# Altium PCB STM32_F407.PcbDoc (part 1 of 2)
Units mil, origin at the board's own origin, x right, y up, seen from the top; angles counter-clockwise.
Board outline 2935.42 x 3745.42 mil, 2 copper layers (TopLayer, BottomLayer); 75 components, 133 nets, 531 pads, 175 vias.
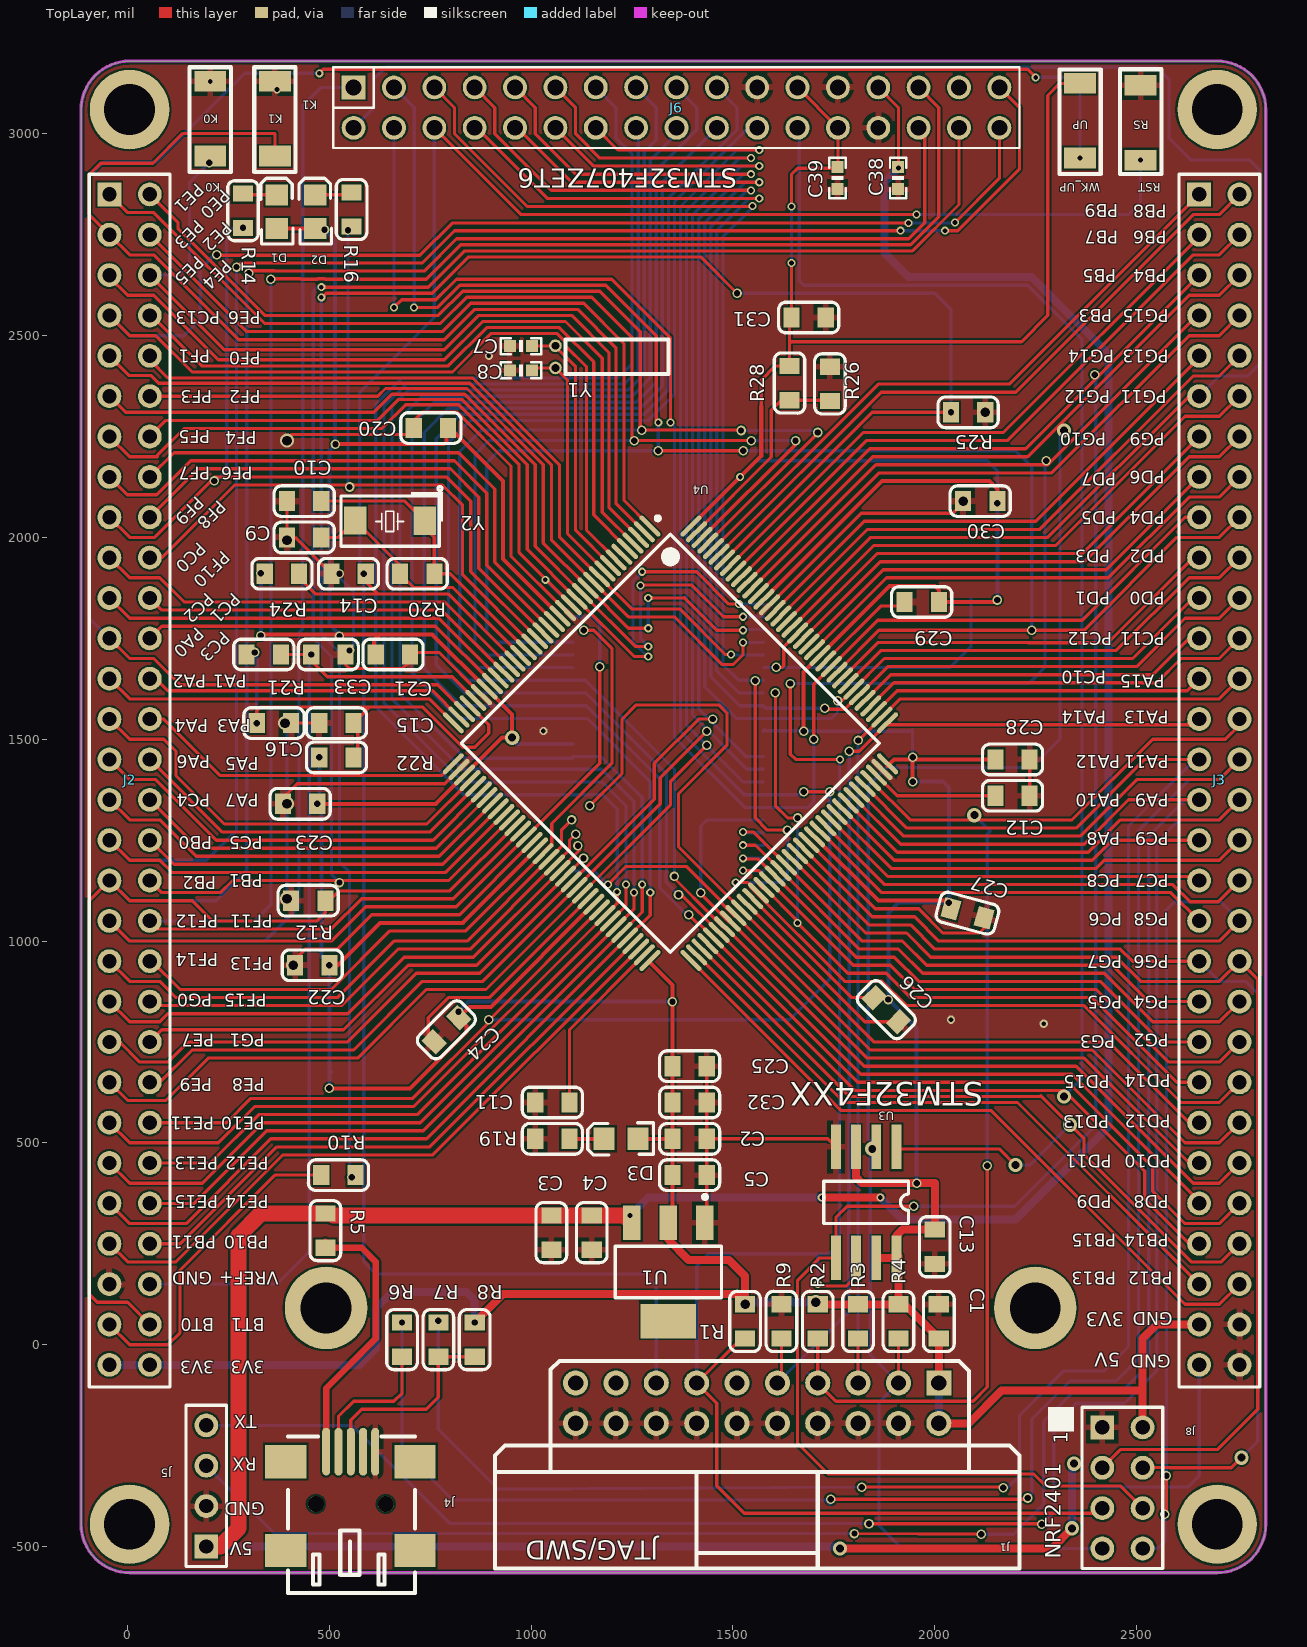
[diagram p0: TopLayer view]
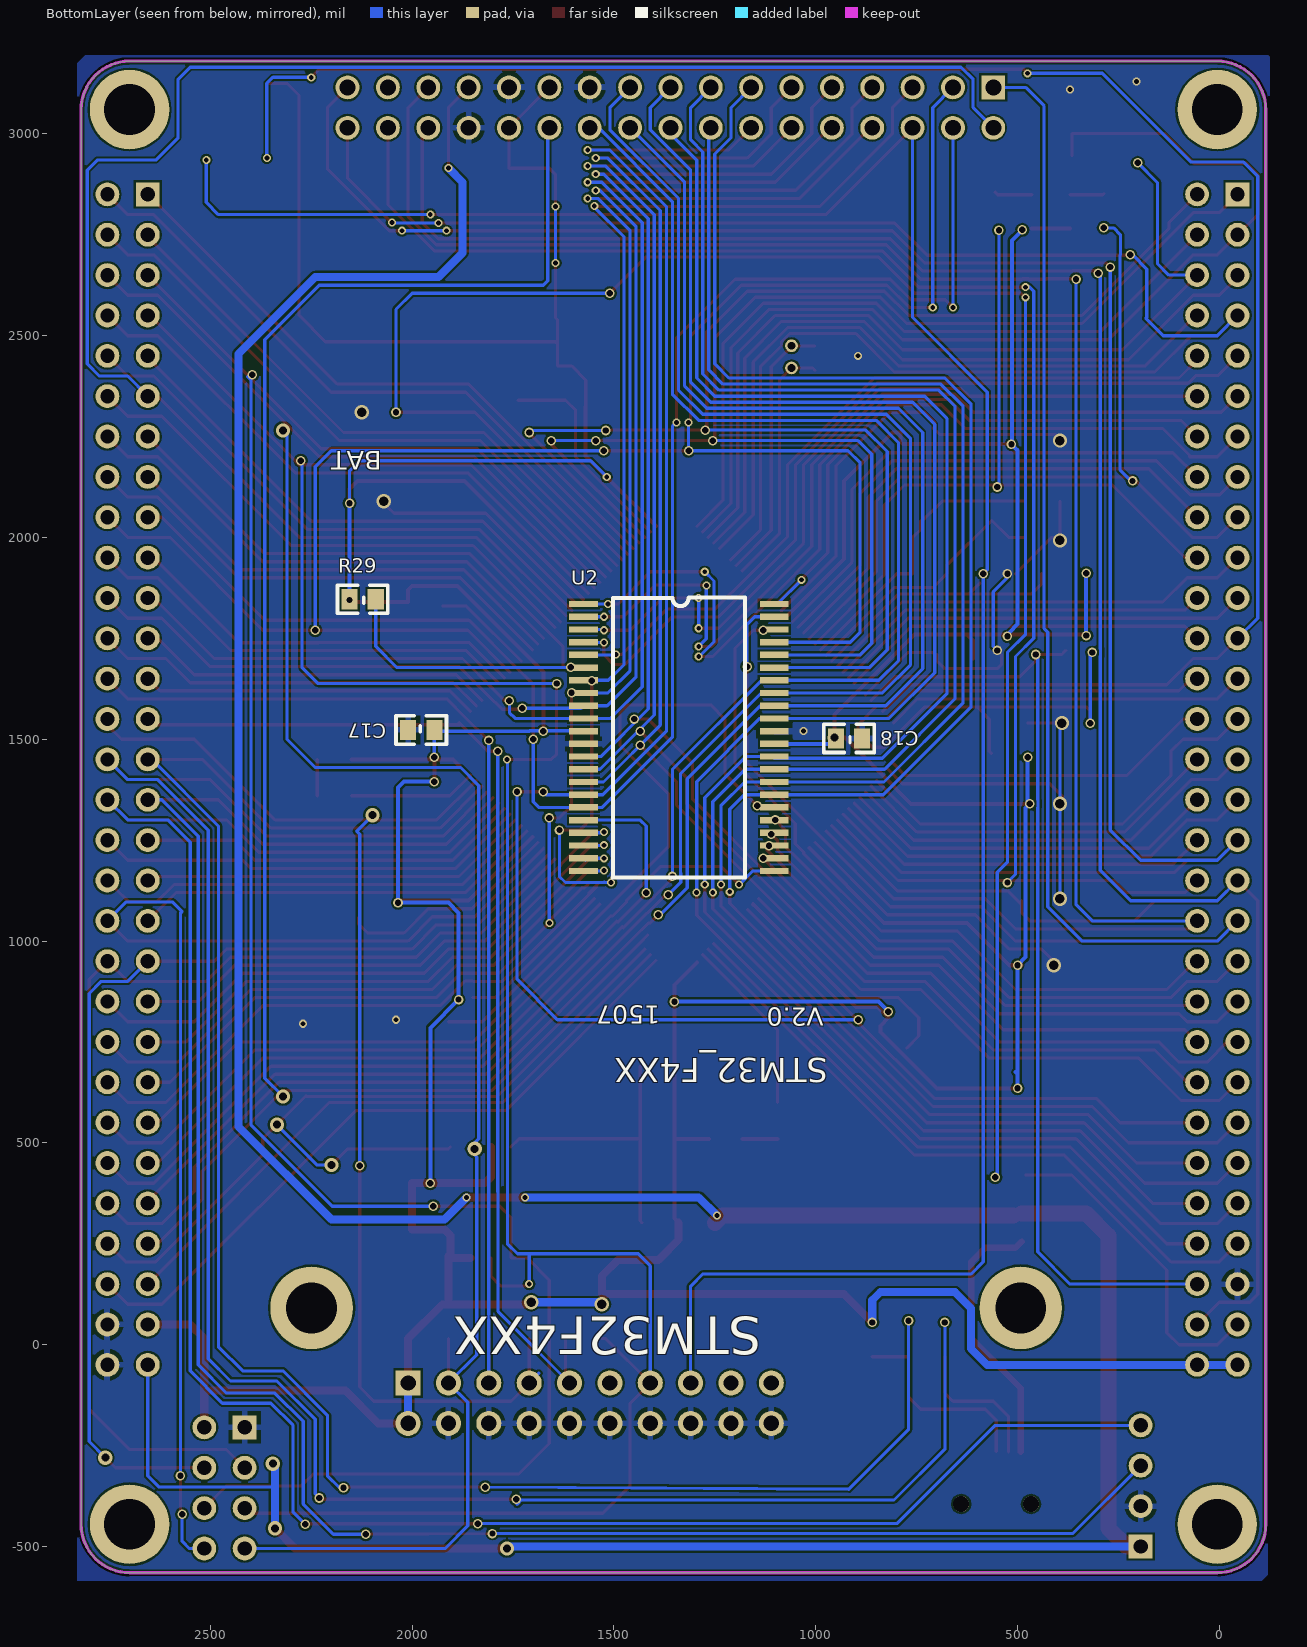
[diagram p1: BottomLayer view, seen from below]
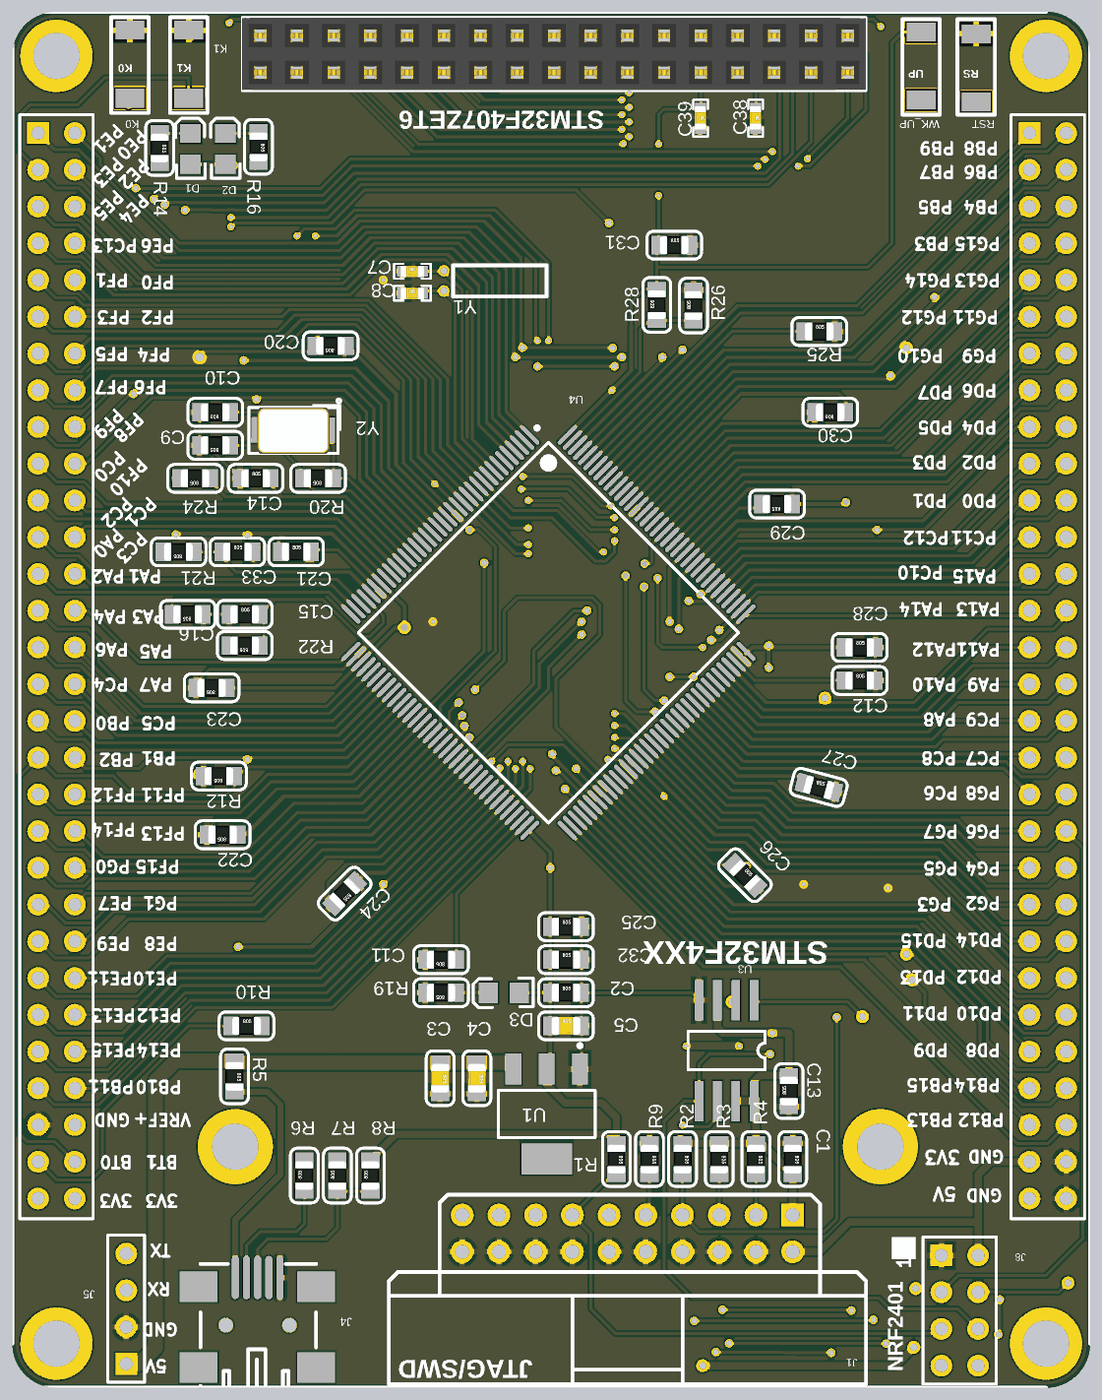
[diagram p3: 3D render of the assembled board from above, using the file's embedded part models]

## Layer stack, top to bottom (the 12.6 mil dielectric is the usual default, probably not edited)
TopSolder: solder mask 0.4, Solder Resist, Dk 3.5
TopLayer: signal copper 1.4
Dielectric1: core 12.6, FR-4, Dk 4.8
BottomLayer: signal copper 1.4
BottomSolder: solder mask 0.4, Solder Resist, Dk 3.5

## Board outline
2820.21,3060 2820.21,-445 cw(c2700,-445) 2700,-565.21 5,-565.21 cw(c5,-445) -115.21,-445 -115.21,3060 cw(c5,3060) 5,3180.21 2700,3180.21 cw(c2700,3060)

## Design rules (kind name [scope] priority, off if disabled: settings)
Clearance [All] p1: gap=5
ComponentClearance [All] p1: gap=1 collisioncheckmode=3 verticalgap=0 showdistances=FALSE
FabricationTestPointUsage TestPointUsage [All] p1: valid=0 allowmultiple=FALSE
FabricationTestpoint Testpoint [(IsPad And (OnTopLayer Or OnBottomLayer))] p1: side=3 testpointundercomponent=TRUE minsize=40 maxsize=100 preferedsize=60 minholesize=20 maxholesize=40 preferedholesize=32 testpointgrid=1 allowsidetop=TRUE allowsidebottom=TRUE usegrid=TRUE gridtolerance=0.01
PlaneClearance [All] p1: clearance=10
PolygonConnect PolygonConnect_1 [All vs (InPadClass('All Pads'))] p1: connectstyle=Relief reliefconductorwidth=15 reliefentries=4 polygonreliefangle="90 Angle" airgapwidth=10
PolygonConnect [All] p2: connectstyle=Direct reliefconductorwidth=10 reliefentries=4 polygonreliefangle="90 Angle" airgapwidth=10
RoutingVias [All] p1: holewidth=12 width=20 viastyle="Through Hole" minholewidth=12 minwidth=20 maxholewidth=24 maxwidth=40
SilkToSolderMaskClearance SilkscreenOverComponentPads [IsPad] p1: minsilkscreentomaskgap=10 clearancetoexposedcopper=TRUE
SolderMaskExpansion [All] p1: expansion=2
Width [All] p1: maxlimit=40 minlimit=8 preferedwidth=8 minimp=50.000000 maximp=50.000000 favimp=50.000000
25 further rules are at their usual default settings.

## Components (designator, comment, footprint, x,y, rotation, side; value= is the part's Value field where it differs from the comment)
C1 "104" RC0603#1 2010,100 r270 top
C2 "104" RC0603#1 1350,510 r0 top
C3 "106" 0805C 1050,320 r270 top
C4 "104" 0805C 1150,320 r270 top
C5 "106" 0805C 1350,420 r0 top
C7 "12pF" 0603C 975,2475 r0 top
C8 "12pF" 0603C 975,2415 r0 top
C9 "22pF" RC0603#1 480,2000 r180 top
C10 "22pF" RC0603#1 480,2090 r180 top
C11 "225" RC0805 1095,600 r180 top
C12 "225" RC0805 2150,1360 r0 top
C13 "104" RC0603#1 2000,200 r90 top
C14 "104" RC0603#1 505,1910 r0 top
C15 "104" RC0603#1 475,1540 r0 top
C16 "106" RC0805 405,1540 r180 top
C17 "104" RC0603#2 1950,1520 r0 bottom
C18 "104" RC0603#2 945,1505 r180 bottom
C20 "104" RC0603#1 794,2271 r180 top
C21 "104" RC0603#1 615,1710 r0 top
C22 "104" RC0603#1 500,940 r180 top
C23 "104" RC0603#1 470,1340 r180 top
C24 "104" RC0603#1 820,810 r225 top
C25 "104" RC0603#1 1350,690 r0 top
C26 "104" RC0603#1 1850,860 r315 top
C27 "104" RC0603#1 2040,1080 r345 top
C28 "104" RC0603#1 2150,1450 r0 top
C29 "104" RC0603#1 2010,1840 r180 top
C30 "104" RC0603#1 2155,2090 r180 top
C31 "104" RC0603#1 1645,2545 r0 top
C32 "106" RC0805 1350,600 r0 top
C33 "104" RC0603#1 455,1710 r0 top
C38 "104" 0603C 1910,2890 r270 top
C39 "104" 0603C 1760,2890 r270 top
D1 "LED" LED0805 370,2765 r270 top
D2 "LED" LED0805 465,2765 r270 top
D3 "LED" LED0805 1265,510 r0 top
J1 "ARM_JTAG" JTAG20P 2010,-95 r180 top
J2 "IO_30X2" IDE2X30 -45,2850 r270 top
J3 "IO_30X2" IDE2X30 2655,2850 r270 top
J4 "USB" MINUSB 492,-265 r270 top
J5 "ISP_COM" HDR1X4 195,-500 r90 top
J6 "TFT_LCD" IDC34-Z 560,3015 r0 top
J8 "NRF2401" DIP2X4-2.54 2420,-205 r270 top (schematic designator U2)
K0 "Jumper" key 205,3130 r270 top
K1 "Jumper" key 365,3130 r270 top
R1 "10K" RC0603#1 1530,100 r270 top
R2 "10K" RC0603#1 1710,100 r270 top
R3 "10K" RC0603#1 1810,100 r270 top
R4 "10K" RC0603#1 1910,100 r270 top
R5 "500mA" RC0805 490,325 r270 top
R6 "22" RC0603#1 680,-30 r90 top
R7 "22" RC0603#1 770,-30 r90 top
R8 "1.5K" RC0603#1 860,-30 r90 top
R9 "10K" RC0603#1 1620,100 r270 top
R10 "510R" RC0603#1 480,420 r0 top
R12 "10K" RC0603#1 490,1100 r180 top
R14 "510R" RC0603#1 286,2852 r270 top
R16 "510R" RC0603#1 555,2855 r270 top
R19 "510R" RC0603#1 1095,510 r180 top
R20 "1M" RC0603#1 760,1910 r180 top
R21 "0R" RC0603#1 380,1710 r180 top
R22 "0R" RC0603#1 560,1455 r180 top
R24 "10K" RC0603#1 425,1910 r180 top
R25 "10K" RC0603#1 2040,2310 r0 top
R26 "NC" RC0603#1 1740,2338 r90 top
R28 "0R" RC0603#1 1640,2340 r90 top
R29 "10K" RC0603#2 2150,1850 r180 bottom
RST "Key" key 2510,2934.96 r90 top
U1 "AMS1117-3.3V" SOT223 1340,180 r180 top
U2 "IS62WV51216BLL-55TLI" TSOP44 1575,1835 r180 bottom
U3 "W25Q16" SOIC8P 1905,470 r180 top
U4 "STM32F407ZET6" LQFP144N 1345,1490 r315 top
WK_UP "Jumper" key 2360,3125 r270 top
Y1 "32.768k" XTAL_2X6 1060,2445 r0 top
Y2 "8MHz" X5032 650,2040 r180 top

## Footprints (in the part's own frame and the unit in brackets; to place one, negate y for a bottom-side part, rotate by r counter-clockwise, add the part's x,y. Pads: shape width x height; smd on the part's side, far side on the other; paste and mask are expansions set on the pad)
0603C [mil]
  rect 30x30 smd: 1(-27.5,-0.94) 2(27,-1)
  silkscreen extent -50,-21 50,19, body extent -32,-17 30,14, height 12
0805C [mil]
  rect 40x50 smd: 1(0,0) 2(85,0)
  silkscreen extent -32,-38 117,38, body extent 3,-25 82,25, height 30
DIP2X4-2.54 [mm]
  rect 1.5x1.5 hole 0.9: 1(0,-0.127)
  round 1.5 hole 0.9: 2(0,2.413) 3(2.54,-0.127) 4(2.54,2.413) 5(5.08,-0.127) 6(5.08,2.413) 7(7.62,-0.127) 8(7.62,2.413)
  silkscreen extent -1.27,-1.4 8.89,3.68
HDR1X4 [mm] "Connector; Header; 4 Position"
  rect 1.5x1.5 hole 0.9: 1(0,0)
  round 1.5 hole 0.9: 2(2.54,0) 3(5.08,0) 4(7.62,0)
  silkscreen extent -1.27,-1.27 8.89,1.27
IDC34-Z [mm]
  rect 1.5x1.5 hole 1: 1(0,2.54)
  round 1.5 hole 1: 2(0,0) 3(2.54,2.54) 4(2.54,0) 5(5.08,2.54) 6(5.08,0) 7(7.62,2.54) 8(7.62,0) 9(10.16,2.54) 10(10.16,0) 11(12.7,2.54) 12(12.7,0) 13(15.24,2.54) 14(15.24,0) 15(17.78,2.54) 16(17.78,0) 17(20.32,2.54) 18(20.32,0) 19(22.86,2.54) 20(22.86,0) 21(25.4,2.54) 22(25.4,0) 23(27.94,2.54) 24(27.94,0) 25(30.48,2.54) 26(30.48,0) 27(33.02,2.54) 28(33.02,0) 29(35.56,2.54) 30(35.56,0) 31(38.1,2.54) 32(38.1,0) 33(40.64,2.54) 34(40.64,0)
  silkscreen extent -1.27,-1.27 41.91,3.81, body extent -1.27,-1.23 41.91,3.77, height 8.5
IDE2X30 [mm]
  rect 1.5x1.5 hole 0.9: 1(0,0)
  round 1.5 hole 0.9: 2(0,2.54) 3(2.54,0) 4(2.54,2.54) 5(5.08,0) 6(5.08,2.54) 7(7.62,0) 8(7.62,2.54) 9(10.16,0) 10(10.16,2.54) 11(12.7,0) 12(12.7,2.54) 13(15.24,0) 14(15.24,2.54) 15(17.78,0) 16(17.78,2.54) 17(20.32,0) 18(20.32,2.54) 19(22.86,0) 20(22.86,2.54) 21(25.4,0) 22(25.4,2.54) 23(27.94,0) 24(27.94,2.54) 25(30.48,0) 26(30.48,2.54) 27(33.02,0) 28(33.02,2.54) 29(35.56,0) 30(35.56,2.54) 31(38.1,0) 32(38.1,2.54) 33(40.64,0) 34(40.64,2.54) 35(43.18,0) 36(43.18,2.54) 37(45.72,0) 38(45.72,2.54) 39(48.26,0) 40(48.26,2.54) 41(50.8,0) 42(50.8,2.54) 43(53.34,0) 44(53.34,2.54) 45(55.88,0) 46(55.88,2.54) 47(58.42,0) 48(58.42,2.54) 49(60.96,0) 50(60.96,2.54) 51(63.5,0) 52(63.5,2.54) 53(66.04,0) 54(66.04,2.54) 55(68.58,0) 56(68.58,2.54) 57(71.12,0) 58(71.12,2.54) 59(73.66,0) 60(73.66,2.54)
  silkscreen extent -1.27,-1.27 75.06,3.81
JTAG20P [mil]
  rect 62x62 hole 38: 1(0,0)
  round 62 hole 38: 2(0,100) 3(100,0) 4(100,100) 5(200,0) 6(200,100) 7(300,0) 8(300,100) 9(400,0) 10(400,100) 11(500,0) 12(500,100) 13(600,0) 14(600,100) 15(700,0) 16(700,100) 17(800,0) 18(800,100) 19(900,0) 20(900,100)
  silkscreen extent -200,-55 1100,460
key [mm]
  rect 1.3x2 smd paste+0 mask+0.2: 1(0,0) 2(4.7,0)
  silkscreen extent -0.89,-1.3 5.72,1.3
LED0805 [mil]
  rect 52x56 smd: 1(0,0) 2(-84,0)
  silkscreen extent -125,-40 38,40
LQFP144N [mm]
  oval 1.75x0.297 smd: 1(-10.575,8.75) 2(-10.575,8.25) 3(-10.575,7.75) 4(-10.575,7.25) 5(-10.575,6.75) 6(-10.575,6.25) 7(-10.575,5.75) 8(-10.575,5.25) 9(-10.575,4.75) 10(-10.575,4.25) 11(-10.575,3.75) 12(-10.575,3.25) 13(-10.575,2.75) 14(-10.575,2.25) 15(-10.575,1.75) 16(-10.575,1.25) 17(-10.575,0.75) 18(-10.575,0.25) 19(-10.575,-0.25) 20(-10.575,-0.75) 21(-10.575,-1.25) 22(-10.575,-1.75) 23(-10.575,-2.25) 24(-10.575,-2.75) 25(-10.575,-3.25) 26(-10.575,-3.75) 27(-10.575,-4.25) 28(-10.575,-4.75) 29(-10.575,-5.25) 30(-10.575,-5.75) 31(-10.575,-6.25) 32(-10.575,-6.75) 33(-10.575,-7.25) 34(-10.575,-7.75) 35(-10.575,-8.25) 36(-10.575,-8.75) 73(10.575,-8.75) 74(10.575,-8.25) 75(10.575,-7.75) 76(10.575,-7.25) 77(10.575,-6.75) 78(10.575,-6.25) 79(10.575,-5.75) 80(10.575,-5.25) 81(10.575,-4.75) 82(10.575,-4.25) 83(10.575,-3.75) 84(10.575,-3.25) 85(10.575,-2.75) 86(10.575,-2.25) 87(10.575,-1.75) 88(10.575,-1.25) 89(10.575,-0.75) 90(10.575,-0.25) 91(10.575,0.25) 92(10.575,0.75) 93(10.575,1.25) 94(10.575,1.75) 95(10.575,2.25) 96(10.575,2.75) 97(10.575,3.25) 98(10.575,3.75) 99(10.575,4.25) 100(10.575,4.75) 101(10.575,5.25) 102(10.575,5.75) 103(10.575,6.25) 104(10.575,6.75) 105(10.575,7.25) 106(10.575,7.75) 107(10.575,8.25) 108(10.575,8.75)
  oval 0.297x1.75 smd: 37(-8.75,-10.575) 38(-8.25,-10.575) 39(-7.75,-10.575) 40(-7.25,-10.575) 41(-6.75,-10.575) 42(-6.25,-10.575) 43(-5.75,-10.575) 44(-5.25,-10.575) 45(-4.75,-10.575) 46(-4.25,-10.575) 47(-3.75,-10.575) 48(-3.25,-10.575) 49(-2.75,-10.575) 50(-2.25,-10.575) 51(-1.75,-10.575) 52(-1.25,-10.575) 53(-0.75,-10.575) 54(-0.25,-10.575) 55(0.25,-10.575) 56(0.75,-10.575) 57(1.25,-10.575) 58(1.75,-10.575) 59(2.25,-10.575) 60(2.75,-10.575) 61(3.25,-10.575) 62(3.75,-10.575) 63(4.25,-10.575) 64(4.75,-10.575) 65(5.25,-10.575) 66(5.75,-10.575) 67(6.25,-10.575) 68(6.75,-10.575) 69(7.25,-10.575) 70(7.75,-10.575) 71(8.25,-10.575) 72(8.75,-10.575) 109(8.75,10.575) 110(8.25,10.575) 111(7.75,10.575) 112(7.25,10.575) 113(6.75,10.575) 114(6.25,10.575) 115(5.75,10.575) 116(5.25,10.575) 117(4.75,10.575) 118(4.25,10.575) 119(3.75,10.575) 120(3.25,10.575) 121(2.75,10.575) 122(2.25,10.575) 123(1.75,10.575) 124(1.25,10.575) 125(0.75,10.575) 126(0.25,10.575) 127(-0.25,10.575) 128(-0.75,10.575) 129(-1.25,10.575) 130(-1.75,10.575) 131(-2.25,10.575) 132(-2.75,10.575) 133(-3.25,10.575) 134(-3.75,10.575) 135(-4.25,10.575) 136(-4.75,10.575) 137(-5.25,10.575) 138(-5.75,10.575) 139(-6.25,10.575) 140(-6.75,10.575) 141(-7.25,10.575) 142(-7.75,10.575) 143(-8.25,10.575) 144(-8.75,10.575)
  silkscreen extent -10.7,-9.3 9.3,9.57
MINUSB [mm]
  oval 3x0.5 smd: 1(0,0) 2(0.009,0.775) 3(0,1.549) 4(0.009,2.324) 5(0.009,3.086)
  rect 2.1x2.6 smd: ""(0.635,5.588) ""(0.635,-2.54) ""(6.223,-2.54) ""(6.223,5.588)
  round 1 hole 1: ""(3.299,3.749) ""(3.299,-0.651)
  silkscreen extent -0.94,-2.41 8.89,5.59
RC0603#1 [mil]
  rect 40x50 smd: 1(0,0) 2(85,0)
  silkscreen extent -32,-38 117,38, body extent 3,-25 82,25, height 30
RC0603#2 [mil]
  rect 40x50 smd: 1(60,-3) 2(-5,-3)
  silkscreen extent -35,-38 90,32
RC0805 [mil]
  rect 40x50 smd: 1(0,0) 2(85,0)
  silkscreen extent -32,-38 117,38, body extent 3,-25 82,25, height 30
SOIC8P [mil]
  rect 24x110 smd: 1(0,-20) 2(50,-20) 3(100,-20) 4(150,-20) 5(150,255) 6(100,255) 7(50,255) 8(0,255)
  silkscreen extent -30,65 180,170
SOT223 [mm] "SOT-223/SC-73; 4 Leads; Body 6.7 x 7.3 mm, inc. leads (LxW max)"
  rect 1.1x2.15 smd: 1(-2.3,-3.1) 2(0,-3.1) 3(2.3,-3.1)
  rect 3.5x2.15 smd: 4(0,3.1)
  silkscreen extent -3.35,-4.85 3.35,1.63
TSOP44 [mm]
  rect 1.8x0.4 smd: 1(-0.009,0.001) 2(-0.009,-0.799) 3(-0.009,-1.599) 4(-0.009,-2.399) 5(-0.009,-3.199) 6(-0.009,-3.999) 7(-0.009,-4.799) 8(-0.009,-5.599) 9(-0.009,-6.399) 10(-0.009,-7.199) 11(-0.009,-7.999) 12(-0.009,-8.799) 13(-0.009,-9.599) 14(-0.009,-10.399) 15(-0.009,-11.199) 16(-0.009,-11.999) 17(-0.009,-12.799) 18(-0.009,-13.599) 19(-0.009,-14.399) 20(-0.009,-15.199) 21(-0.009,-15.999) 22(-0.009,-16.799) 23(11.991,-16.799) 24(11.991,-15.999) 25(11.991,-15.199) 26(11.991,-14.399) 27(11.991,-13.599) 28(11.991,-12.799) 29(11.991,-11.999) 30(11.991,-11.199) 31(11.991,-10.399) 32(11.991,-9.599) 33(11.991,-8.799) 34(11.991,-7.999) 35(11.991,-7.199) 36(11.991,-6.399) 37(11.991,-5.599) 38(11.991,-4.799) 39(11.991,-3.999) 40(11.991,-3.199) 41(11.991,-2.399) 42(11.991,-1.599) 43(11.991,-0.799) 44(11.991,0.001)
  silkscreen extent 1.83,-17.2 10.16,0.4
X5032 [mil]
  rect 55.12x70.24 smd: 1(-86,-1)
  rect 55.12x70 smd: 2(86,-2)
  silkscreen extent -131,-86 121,62, body extent -98,-63 98,63, height 39
XTAL_2X6 [mm]
  round 0.8 hole 0.5: 1(0,-0.635) 2(0,0.762)
  silkscreen extent 0.64,-1.02 7.11,1.14, body extent 0.91,-0.94 6.91,1.05, height 2

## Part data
C1 C2 C17 C18 C38 C39: library part Cap, "Capacitor"
C3 C4 C5: library part 0805C, "Capacitor"
C7 C8 C9 C10 C11 C12 C14 C15 C16 C20 C21 C22 C23 C24 C25 C26 C27 C28 C29 C30 C31 C33: library part CAP, "Capcitor"
C13: library part CAP
C32: library part "CAPACITOR POL", "Capacitor"
J1: library part JTAG, "JTAG"
J2 J3: library part "Header 30X2", "Header, 30-Pin, Dual row"
J4: library part usb
J5: library part "Header 4", "Header, 4-Pin"
J8: library part "Header 4X2", "Header, 4-Pin, Dual row"
K0 K1 WK_UP: "Jumper Wire"
R1 R2 R3 R4 R5 R6 R7 R8 R14 R16 R19: library part RES
R9 R10 R12 R21 R22 R24 R25 R26 R28 R29: library part Res2, "Resistor"
R20: library part Res1, "Resistor"
RST: library part Jumper, "Jumper Wire"
U1: library part 11
U3: library part W25X16
Y1: library part CRYSTAL, "Crystal 8MHz PLUG"
Y2: library part XTAL, "Crystal Oscillator"

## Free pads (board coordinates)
  round 196.85 hole 125.98: ""(5,-445) ""(5,3060) ""(2700,-445) ""(2700,3060)
  round 204.72 hole 125.98: ""(492,91) ""(2249,91)

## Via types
v1: diameter 23.62, hole 15.75, TopLayer to BottomLayer, 92 vias
v2: diameter 20, hole 12, TopLayer to BottomLayer, 62 vias
v3: diameter 35.43, hole 19.68, TopLayer to BottomLayer, 11 vias
v4: diameter 35.43, hole 23.62, TopLayer to BottomLayer, 10 vias

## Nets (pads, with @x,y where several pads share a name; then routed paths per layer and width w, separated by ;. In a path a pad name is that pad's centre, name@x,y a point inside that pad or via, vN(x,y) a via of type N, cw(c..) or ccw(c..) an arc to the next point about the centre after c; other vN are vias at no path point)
3V3: C1.2 C2.1 C5.1 C13.2 C17.2 C18.2 C20.1 C21.1 C22.1 C23.1 C24.1 C25.1 C26.1 C27.1 C28.1 C29.1 C30.1 C31.1 C32.1 C39.1 D1.1 D2.1 D3.1 J1.1 J1.2 J2.59 J2.60 J3.57 J6.23 J6.26 J8.2 R1.1 R2.1 R3.1 R4.1 R8.2 R22.2 R24.2 R28.2 R29.2 U1.2 U2.11 U2.33 U3.3 U3.7 U3.8 U4.17 U4.30 U4.39 U4.52 U4.62 U4.72 U4.84 U4.95 U4.108 U4.121 U4.131 U4.144 WK_UP.1 | length 19846.7
  TopLayer w8: U4.84@1548.92,1105.13 1794.05,860 C26.1@1850,860 ; 1570,2325 1570,2390 1605,2425 R28.2@1640,2425 1640,2480 ; v2(1645,2680) C31.1@1645,2545 1640,2540 1640,2480 ; v2(1645,2820) 1645,2900 1660,2915 1760,2915 J6.26@1760,3015 J6.23@1660,3115 ; WK_UP.1@2360,3125 2310,3125 2280,3095 2280,2550 2215,2485 1645,2485 1640,2480
  TopLayer w10: v1(330,1757) 333,1760 625,1760 ; D1.1@370,2765 D2.1@465,2765 ; v1(470,1340) 763.5,1340 U4.39@834.85,1411.36 927.5,1504 v3(953,1504) ; C22.1@490,940 v1(500,940) 520,940 625,1045 830.4,1045 U4.52@1015.81,1230.4 ; v1(500,635) 700,635 840,775 840,790 C24.1@820,810 846.81,836.81 900.6,836.81 U4.62@1155,1091.21 ; v1(515,2231) 784,2231 790,2237 790,2260 810,2260 930,2140 930,1946.76 U4.17@1071.48,1805.27 ; C21.1@610,1700 610,1745 625,1760 ; v3@953,1515 953,1561.85 U4.30@890.53,1624.32 754.85,1760 625,1760 ; D3.1@1265,510 C2.1@1350,510 ; U4.72@1294.19,947.01 1350,891.21 C25.1@1350,690 C32.1@1350,600 C2.1@1350,510 ; U1.2@1340,302.05 1350,312.05 C5.1@1350,420 C2.1@1350,510 ; U4.144@1395.81,2027.99 v2(1517.82,2150) 1570,2202.18 1570,2325 ; U4.131@1576.76,1847.03 1869.73,2140 2135,2140 2155,2120 C30.1@2155,2090 ; v1(1675,1520) 1675,1666.89 U4.121@1715.95,1707.84 1888.11,1880 2000,1880 2010,1870 C29.1@2010,1840 2150,1840 v1(2155,1845) ; U4.95@1702.03,1258.24 1860.27,1100 C27.1@2040,1100 ; U4.108@1882.99,1434.19 1898.79,1450 v1@1945,1450 ; U3.8@1910,220 1910,275 ; v1(1945,1395) v1@1945,1450 ; v1(1945,1455) v1@1945,1450 ; C28.1@2150,1450 v1@1945,1450
  TopLayer w20: v1(860,55) 930,125 1530,125 1530,170 1490,210 1390,210 1340,260 U1.2@1340,302.05 ; R2.1@1710,100 R3.1@1810,100 R4.1@1910,100 ; U3.3@1805,490 1805,415 1820,400 2000,400 C13.2@2000,285 1920,285 1910,275 1905,270 U3.8@1905,215 U3.7@1855,215 ; U3.8@1910,220 R4.1@1910,100 ; J1.2@2010,-195 2084,-195 2165,-114 2515,-114 ; J1.1@2010,-95 C1.2@2010,15 1925,100 R4.1@1910,100 ; J8.2@2515,-205 2515,-114 ; J3.57@2655,50 2550,50 2515,15 2515,-114
  BottomLayer w8: v2(1517.82,2150) 1557.82,2190 2130,2190 2155,2165 v1(2155,2085) ; U2.11@1575.35,1520.06 1576.1,1520.81 1708.62,1520.81 1709.37,1520.06 1942.06,1520.06 C17.2@1945,1523 v1(1945,1455) ; v2(1645,2680) v2(1645,2820)
  BottomLayer w10: v1(330,1757) v1(330,1911) ; v1(475,1455) 475,1345 v1(470,1340) 480,1330 480,960 v1(500,940) 500,670 ; v1(488,2762) 514,2736 514,2231 v1(515,2231) 500,2216 500,1785 v1@520,1765 ; v1(500,635) 500,670 ; 505,675 500,670 ; v1(820,825) 845,850 v1(1350,850) ; C18.2@950,1502 963.43,1488.57 U2.33@1102.91,1488.57 ; U2.11@1575.35,1520.06 U2.11@1578.01,1522.72 ; v1(1945,1395) 2020,1395 2035,1380 v1(2035,1095) 1910,1095 1885,1070 v1(1885,855) 1955,785 v1(1955,400) ; v1(2155,1845) v1(2155,2085)
  BottomLayer w20: J2.59@-45,-50 J2.60@55,-50 575,-50 615,-10 615,90 655,130 840,130 860,110 v1(860,55) ; v4(1530,100) 1535,105 v4(1705,105) ; J1.2@2010,-195 J1.1@2010,-95
  other v1: 525,1755
5V: C3.1 C4.1 C38.1 J3.59 J5.1 J6.27 R5.1 U1.3 | length 9089.8
  TopLayer w8: J6.27@1860,3115 1910,3065 1910,2920 C38.1@1900,2910
  TopLayer w20: v2(1720,365) v2(1865,365) ; v3(1765,-505) 2290,-505 v3(2340,-455) v3@2335,-455 ; J3.59@2650,-55 J3.59@2655,-50
  TopLayer w40: J5.1@195,-500 230,-500 275,-455 275,270 330,325 R5.1@490,325 ; R5.1@510,320 C3.1@1050,320 C4.1@1150,320 1231.5,320 U1.3@1249.45,302.05
  BottomLayer w8: 2340,-354 2341,-353 2627,-353 2655,-325 J3.59@2655,-50
  BottomLayer w20: J5.1@195,-500 1760,-500 v3(1765,-505) ; v2(1245,320) 1290,365 v2(1720,365) ; v2(1865,365) 1920,310 2200,310 2430,540 2430,2455 2240,2645 1935,2645 1875,2705 1875,2880 v2(1910,2915) ; v3(2340,-455) 2340,-354 v3@2340,-305
  other v3: 2345,-295
BOOT0: R10.2 R25.1 U4.138 | length 4833.4
  TopLayer w8: v2(480,2595) 481.87,2595 491.87,2605 755,2605 845,2695 1420,2695 v1(1510,2605) ; U4.138@1479.32,1944.47 1844.85,2310 v1(2040,2310)
  BottomLayer w8: v2(480,2595) 480,1760 525,1715 525,1195 550,1170 550,420 v1(555,415) ; v1(1510,2605) 2000,2605 2040,2565 v1(2040,2310)
DCMI_D6: J2.5 U4.4 | length 1877.4
  TopLayer w8: J2.5@-45,2650 -45,2645 0,2600 65,2600 225,2440 785,2440 880,2535 1085,2535 1176,2444 1176,2062.66 U4.4@1252.44,1986.23
DCMI_D7: J2.8 U4.5 | length 1723.6
  TopLayer w8: J2.8@55,2550 58.38,2550 183.38,2425 795,2425 890,2520 1070,2520 1155,2435 1155,2055.82 U4.5@1238.52,1972.31
F_CS: J3.54 U3.1 U4.75 | length 2186.1
  TopLayer w8: U4.75@1423.64,979.85 1788.5,615 2261,615 2263,617 2370,510 2370,470 2635,205 2710,205 J3.54@2755,250 ; U3.1@1905,490 1910,485 2160,485 v3(2200,445)
  BottomLayer w8: v3(2200,445) 2235,445 v3(2335,545)
FSMC_A0: J2.10 U2.5 U4.10 | length 1937.6
  TopLayer w8: J2.10@55,2450 55,2440 100,2395 855,2395 1070,2180 1070,2001.63 U4.10@1168.92,1902.71 1248.63,1823 1368,1823 1481,1710 v2(1495,1710)
  BottomLayer w8: v2(1495,1710) 1495.96,1709.04 U2.5@1575.35,1709.04
FSMC_A1: J2.9 U2.4 U4.11 | length 2086.9
  TopLayer w8: J2.9@-45,2450 4,2401 58.49,2401 77.49,2382 848,2382 1050,2180 1050,1993.79 U4.11@1155,1888.79 1240.79,1803 1355,1803 1473,1685 1500,1685 1525,1710 v2(1525,1740)
  BottomLayer w8: v2(1525,1740) 1574.82,1740 U2.4@1575.35,1740.54
FSMC_A2: J2.12 U2.3 U4.12 | length 1997.7
  TopLayer w8: J2.12@55,2350 620,2350 639,2369 841,2369 1030,2180 1030,1985.95 U4.12@1141.08,1874.87 1240.95,1775 v2(1290,1775) ; v2(1290,1850) 1378,1850 1379,1851 1460,1770 v2(1525,1770)
  BottomLayer w8: v2(1290,1775) v2(1290,1850) ; v2(1525,1770) 1527.03,1772.03 U2.3@1575.35,1772.03
FSMC_A3: J2.11 U2.2 U4.13 | length 2242.1
  TopLayer w8: J2.11@-45,2350 -5,2310 610,2310 655,2355 835,2355 1010,2180 1010,1978.11 U4.13@1127.16,1860.95 1258.11,1730 v2(1290,1730) ; v2@1272,1882 1398,1882 1476.47,1803.53 v2(1525,1803.53)
  BottomLayer w8: v2(1271,1881) 1271,1749 v2(1290,1730) ; v2(1525,1803.53) U2.2@1575.35,1803.53
FSMC_A4: J2.14 U2.1 U4.14 | length 2229.7
  TopLayer w8: J2.14@55,2250 95,2290 620,2290 672,2342 828,2342 990,2180 990,1970.27 U4.14@1113.24,1847.03 1255.27,1705 v2(1290,1705) ; v2(1275,1915) 1410,1915 1490,1835 v2(1515,1835)
  BottomLayer w8: v2(1275,1915) 1252,1892 1252,1741.13 1288.13,1705 v2(1290,1705) ; v2(1515,1835) U2.1@1575.35,1835.02
FSMC_A5: J2.13 U2.44 U4.15 | length 1646.4
  TopLayer w8: J2.13@-45,2250 5,2200 74,2200 74,2204 140,2270 630,2270 689,2329 821,2329 970,2180 970,1962.44 U4.15@1099.32,1833.11
  BottomLayer w8: v2(1035,1895) 1094.98,1835.02 U2.44@1102.91,1835.02
FSMC_A6: J2.37 J6.1 U2.43 U4.50 | length 4496.3
  TopLayer w8: J2.37@-45,1050 5,1000 505,1000 590,1085 814.73,1085 U4.50@987.97,1258.24 1170,1440.27 v1(1170,1680)
  BottomLayer w8: J2.37@-45,1050 5,1000 340,1000 425,1085 425,1765 434.19,1774.19 434.19,3069.19 480,3115 J6.1@560,3115 ; U2.43@1102.91,1803.53 1151.47,1803.53 1170,1785 v1(1170,1680)
FSMC_A7: J2.40 U2.42 U4.53 | length 1811.5
  TopLayer w8: J2.40@55,950 60,950 130,880 505,880 650,1025 838.24,1025 U4.53@1029.73,1216.48 1029.73,1219.52 1050.88,1240.67 1050.88,1289.12 1050,1290 1200,1440 1200,1725 1155,1770 v1(1130,1770)
FSMC_A8: J2.39 U2.27 U4.54 | length 1388.6
  TopLayer w8: J2.39@-45,950 5,900 80,900 120,860 520,860 660,1000 841.08,1000 U4.54@1043.65,1202.56 1075,1233.92 1075,1275 v1(1100,1300)
FSMC_A9: J2.42 U2.26 U4.55 | length 1249.2
  TopLayer w8: J2.42@55,850 65,840 530,840 670,980 848.92,980 U4.55@1057.56,1188.65 1095,1226.08 1095,1250 v1(1110,1265)
FSMC_A10: J2.41 U2.25 U4.56 | length 1364
  TopLayer w8: J2.41@-45,850 5,800 80,800 100,820 545,820 685,960 856.76,960 U4.56@1071.48,1174.73 1071.48,1176.32 v1@1120.98,1225.81
  other v1: 1115.81,1236.38
FSMC_A11: J2.44 U2.24 U4.57 | length 1263.1
  TopLayer w8: J2.44@55,750 85,780 535,780 695,940 864.6,940 U4.57@1085.4,1160.81 v1(1129.6,1205)
FSMC_A12: J3.44 U2.22 U4.87 | length 1498.4
  TopLayer w8: v2(1525,1175) 1562.56,1175 U4.87@1590.68,1146.89 1797.56,940 1890,940 1950,880 2400,880 2580,700 2705,700 J3.44@2755,750
  BottomLayer w8: v2(1525,1175) 1526.39,1173.61 U2.22@1575.35,1173.61
FSMC_A13: J3.43 U2.21 U4.88 | length 1377.2
  TopLayer w8: v2(1525,1205) 1525,1203 1562.4,1203 U4.88@1604.6,1160.81 1805.4,960 1900,960 1960,900 2410,900 2560,750 J3.43@2655,750
  BottomLayer w8: v2(1525,1205) 1525.1,1205.1 U2.21@1575.35,1205.1 U2.21@1570.25,1200
FSMC_A14: J3.42 U2.20 U4.89 | length 1484.7
  TopLayer w8: v2(1525,1237.5) 1555.74,1237.5 U4.89@1618.52,1174.73 1813.24,980 1910,980 1970,920 2420,920 2540,800 2705,800 J3.42@2755,850
  BottomLayer w8: v2(1525,1237.5) 1525.5,1237.5 1528,1240 1531.4,1236.6 U2.20@1575.35,1236.6
FSMC_A15: J3.41 U2.19 U4.90 | length 1369.6
  TopLayer w8: v2(1525,1270) 1551.08,1270 U4.90@1632.44,1188.65 ; U4.90@1631.9,1188.1 1820,1000 1920,1000 1980,940 2440,940 2530,850 J3.41@2655,850 J3.41@2645,840
  BottomLayer w8: v2(1525,1270) 1526.91,1268.09 U2.19@1575.35,1268.09
FSMC_A16: J3.49 U2.18 U4.80 | length 1836.5
  TopLayer w8: v1@1420,1117.69 U4.80@1490.74,1046.95 ; U4.80@1493.24,1049.45 1832.69,710 2370,710 2630,450 J3.49@2655,450
  BottomLayer w8: v1(1420,1120) 1420,1285 1434.59,1299.59 U2.18@1575.35,1299.59
FSMC_A17: J3.48 U2.23 U4.81 | length 1989.9
  TopLayer w8: v2(1190,1140) 1235,1185 1384.43,1185 1468.53,1100.9 1468.53,1097 U4.81@1504.66,1060.87 ; U4.81@1507.16,1063.37 1840.53,730 2390,730 2620,500 2705,500 J3.48@2755,550
  BottomLayer w8: U2.23@1102.91,1173.61 1156.39,1173.61 v2(1190,1140)
FSMC_A18: J3.47 U2.28 U4.82 | length 2485.3
  TopLayer w8: v1(1145,1335) 1225,1415 1225,1550 1260,1585 1465,1585 1485,1565 1485,1485 1365,1365 1365,1233.37 U4.82@1521.08,1077.29 1848.37,750 2430,750 2630,550 J3.47@2655,550
FSMC_D0: J3.46 J6.5 U2.7 U4.85 | length 4436.5
  TopLayer w8: J6.5@760,3115 810,3065 810,3000 990,2820 1547.64,2820 v2(1548.64,2821) ; v2(1506.89,1145) 1536.89,1145 U4.85@1562.84,1119.05 ; U4.85@1543.44,1133.44 1776.89,900 1848.99,900 1849.81,900.82 1869.18,900.82 1930,840 2370,840 2610,600 2705,600 J3.46@2755,650 ; v1(1555,1645) 1555,1305 1585,1275 v1(1635,1275)
  BottomLayer w8: v2(1506.89,1145) 1522.5,1145 1523.75,1146.25 1523.75,1145 1620,1145 1635,1160 v1(1635,1275) ; v2(1548.64,2821) 1548.64,2818.64 1475,2745 1475,1685 1513.95,1646.05 U2.7@1575.35,1646.05
FSMC_D1: J3.45 J6.8 U2.8 U4.86 | length 4046
  TopLayer w8: J6.8@860,3015 865,3015 1040,2840 v2(1565,2840) ; U4.86@1564.86,1139.86 U4.86@1574.26,1130.47 ; U4.86@1576.76,1132.97 1659.73,1050 v2(1659.73,1045) 1784.73,920 1880,920 1940,860 2390,860 2600,650 J3.45@2655,650 ; v1(1605,1615) 1605,1335 1635,1305 v1(1660,1305)
  BottomLayer w8: v2(1565,2840) 1540,2840 1460,2760 1460,1670 1515.45,1614.55 U2.8@1575.35,1614.55 ; v2(1659.73,1045) 1660,1045.27 v1(1660,1305)
FSMC_D2: J3.22 J6.7 U2.9 U4.114 | length 3538.7
  TopLayer w8: J6.7@860,3115 910,3065 910,3000 1050,2860 v2(1545,2860) ; v1(1727,1577) 1729.81,1574.19 1777.17,1574.19 U4.114@1813.39,1610.4 1882.98,1680 2500,1680 2620,1800 2705,1800 J3.22@2755,1850
  BottomLayer w8: v2(1545,2860) 1535,2860 1445,2770 1445,1655 1516.95,1583.05 U2.9@1575.35,1583.05 1581.41,1577 v1(1727,1577)
FSMC_D3: J3.21 J6.10 U2.10 U4.115 | length 3385.4
  TopLayer w8: J6.10@960,3015 965,3015 1100,2880 v2(1565,2880) ; v1(1759,1595) 1770.15,1595 U4.115@1799.47,1624.32 1875.15,1700 1880.15,1700 2490,1700 2640,1850 J3.21@2655,1850
  BottomLayer w8: v2(1565,2880) 1530,2880 1430,2780 1430,1630 1508.44,1551.56 U2.10@1575.35,1551.56 1744.56,1551.56 1759,1566 v1(1759,1595)
FSMC_D4: J2.43 J6.9 U2.13 U4.58 | length 4231.8
  TopLayer w8: J2.43@-45,750 -20,750 30,700 100,700 150,750 545,750 715,920 872.44,920 U4.58@1099.32,1146.89 1100.91,1146.89 1305,1350.97 1305,1440 1415,1550 v1(1450,1550) ; J6.9@960,3115 1010,3065 1010,3000 1110,2900 v2(1545,2900)
  BottomLayer w8: v2(1545,2900) 1525,2900 1415,2790 1415,1575 1532.93,1457.07 U2.13@1575.35,1457.07
FSMC_D5: J2.46 J6.12 U2.14 U4.59 | length 4008.7
  TopLayer w8: J2.46@55,650 80,650 160,730 560,730 730,900 880.27,900 U4.59@1113.24,1132.97 1320,1339.73 1320,1405 v1(1435,1520) ; J6.12@1060,3015 1155,2920 v2(1565,2920)
  BottomLayer w8: v2(1565,2920) 1520,2920 1400,2800 1400,1560 1534.43,1425.57 U2.14@1575.35,1425.57
FSMC_D6: J2.45 J6.11 U2.15 U4.60 | length 4230.3
  TopLayer w8: J2.45@-45,650 0,605 95,605 200,710 570,710 740,880 888.11,880 U4.60@1127.16,1119.05 1345,1336.89 1345,1395 v1(1435,1485) ; J6.11@1060,3115 1110,3065 1110,3000 1170,2940 v2(1545,2940)
  BottomLayer w8: v2(1545,2940) 1515,2940 1385,2810 1385,1535 1525.92,1394.08 U2.15@1575.35,1394.08
FSMC_D7: J2.48 J6.14 U2.16 U4.63 | length 5105.7
  TopLayer w8: J2.48@55,550 245,550 305,610 706.63,610 901.63,805 901.63,810 U4.63@1168.92,1077.29 ; J6.14@1160,3015 1215,2960 v2(1565,2960) ; v1(1675,1370) v1(1740,1370)
  BottomLayer w8: v1(895,805) 1640,805 1740,905 v1(1740,1370) ; v2(1565,2960) 1510,2960 1370,2820 1370,1520 1527.42,1362.58 U2.16@1575.35,1362.58 1667.58,1362.58 v1(1675,1370)
FSMC_D8: J2.47 J6.13 U2.29 U4.64 | length 4609.5
  TopLayer w8: J2.47@-45,550 5,500 225,500 315,590 709.47,590 U4.64@1182.84,1063.37 1213,1093.53 v2(1213,1122)
  BottomLayer w8: J6.13@1160,3115 1210,3065 1210,2990 1250,2950 1250,2430 1215,2395 680,2395 615,2330 615,1580 832.42,1362.58 U2.29@1102.91,1362.58 1177.42,1362.58 1213,1327 v2(1213,1122)
FSMC_D9: J2.50 J6.16 U2.30 U4.65 | length 4401.4
  TopLayer w8: J2.50@55,450 205,450 325,570 717.31,570 U4.65@1196.76,1049.45 1235,1087.69 v2(1235,1140)
  BottomLayer w8: v2(1235,1140) 1235,1335 1175.92,1394.08 U2.30@1102.91,1394.08 830.92,1394.08 635,1590 635,2325 690,2380 1230,2380 1265,2415 1265,3010 J6.16@1260,3015
FSMC_D10: J2.49 J6.15 U2.31 U4.66 | length 4699.4
  TopLayer w8: J2.49@-45,450 5,400 185,400 335,550 725.15,550 U4.66@1210.68,1035.53 1255,1079.85 v2(1255,1120)
  BottomLayer w8: v2(1255,1120) 1255,1345 1174.43,1425.57 U2.31@1102.91,1425.57 829.43,1425.57 655,1600 655,2325 695,2365 1240,2365 1280,2405 1280,2955 1310,2985 1310,3065 J6.15@1260,3115
FSMC_D11: J2.52 J6.18 U2.32 U4.67 | length 4505
  TopLayer w8: J2.52@55,350 165,350 345,530 732.98,530 U4.67@1224.6,1021.61 1275,1072.02 v2(1275,1140)
  BottomLayer w8: v2(1275,1140) 1275,1355 1172.93,1457.07 U2.32@1102.91,1457.07 1102.91,1453 835,1453 675,1613 675,2295 730,2350 1250,2350 1295,2395 1295,2935 1360,3000 J6.18@1360,3015
FSMC_D12: J2.51 J6.17 U2.35 U4.68 | length 4765.5
  TopLayer w8: J2.51@-45,350 5,300 145,300 355,510 740.82,510 U4.68@1238.52,1007.69 1295,1064.18 v2(1295,1120)
  BottomLayer w8: v2(1295,1120) 1295,1395 1138.44,1551.56 U2.35@1102.91,1551.56 818.44,1551.56 705,1665 705,2280 760,2335 1260,2335 1310,2385 1310,2910 1410,3010 1410,3065 J6.17@1360,3115
FSMC_D13: J3.52 J6.20 U2.36 U4.77 | length 4721.8
  TopLayer w8: v1(1390,1065) 1410,1045 1414.18,1045 U4.77@1451.48,1007.69 1809.18,650 2330,650 2540,440 2540,380 2620,300 2705,300 J3.52@2755,350
  BottomLayer w8: v1(1390,1065) 1385.57,1065 1318.37,1132.2 1318.37,1401.63 1136.95,1583.05 U2.36@1102.91,1583.05 826.95,1583.05 735,1675 735,2260 795,2320 1270,2320 1325,2375 1325,2880 J6.20@1460,3015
